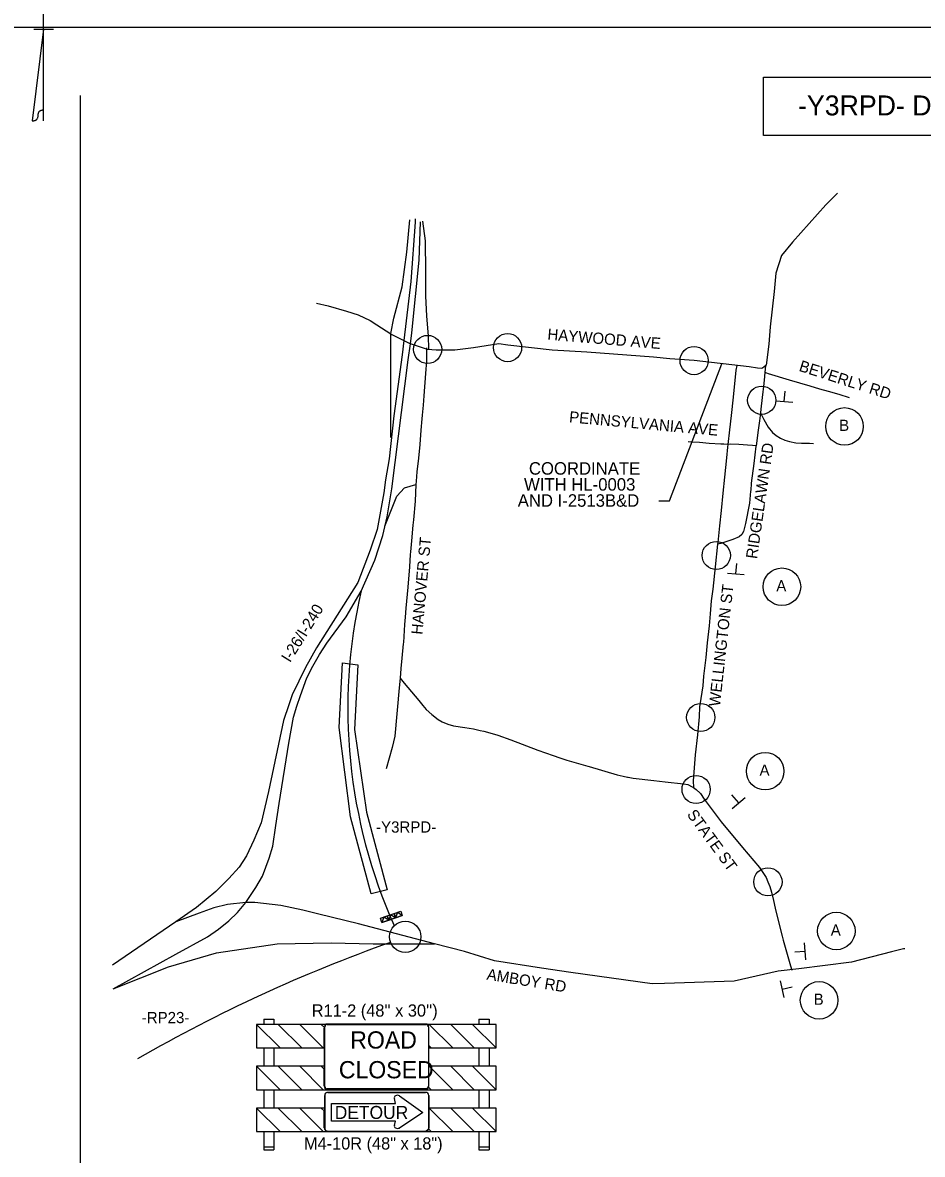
# Model space of a CAD drawing. Extents: x 886234 to 968767, y 455416 to 684046.
# Drawn here: x 922261 to 931269, y 524412 to 535743 of the extents above; entities that cross this region are included whole.
import ezdxf

# ---------------------------------------------------------------- set-up
doc = ezdxf.new("R2010")
doc.units = 0
for name, color, linetype in [('Scratch_Level_3', 7, 'Continuous'), ('TC CONSTRUCTION PROPOSED ROADWAY SHADE', 7, 'Continuous'), ('TC DEV BARRICADE', 7, 'Continuous'), ('TC DEV SIGN', 7, 'Continuous'), ('TC DEV SIGN BLACK 239', 7, 'Continuous'), ('TC DEV SIGN BLACK ZERO', 7, 'Continuous'), ('TC DEV SIGN ORANGE', 7, 'Continuous'), ('TC DEV SIGN WHITE', 7, 'Continuous'), ('TC LABEL TEXT', 7, 'Continuous'), ('TC SHEET LAYOUT SHAPE', 7, 'Continuous')]:
    doc.layers.add(name, color=color, linetype=linetype)

msp = doc.modelspace()

# ---------------------------------------------------------------- linework, layer by layer
at = {"layer": 'Scratch_Level_3'}
msp.add_line((904674, 535699), (939863, 535699), dxfattribs=at)
at = {"layer": 'TC CONSTRUCTION PROPOSED ROADWAY SHADE'}
msp.add_lwpolyline([(925750, 527019), (925544, 527792), (925430, 528686), (925464, 529333), (925617, 529313), (925584, 528666), (925704, 527839), (925910, 527059)], close=True, dxfattribs=at)
at = {"layer": 'TC DEV BARRICADE'}
for p, q in [((925877, 526788), (925911, 526800)), ((925911, 526800), (925945, 526811)), ((925926, 526757), (925911, 526800)), ((925911, 526800), (925926, 526757)), ((925945, 526811), (925926, 526757)), ((925945, 526811), (925980, 526823)), ((925945, 526811), (925945, 526811)), ((925945, 526811), (925945, 526811)), ((925994, 526780), (925945, 526811)), ((925980, 526823), (926013, 526834)), ((925994, 526780), (925980, 526823)), ((925980, 526823), (925994, 526780)), ((926013, 526834), (925994, 526780)), ((926013, 526834), (926048, 526845)), ((926013, 526834), (926013, 526834)), ((926013, 526834), (926013, 526834)), ((926062, 526803), (926013, 526834)), ((926048, 526845), (926062, 526803)), ((925843, 526777), (925877, 526788)), ((925857, 526734), (925843, 526777)), ((925877, 526788), (925857, 526734)), ((925877, 526788), (925877, 526788)), ((925877, 526788), (925877, 526788)), ((925926, 526757), (925877, 526788)), ((924603, 525713), (924603, 525477)), ((924819, 525713), (924603, 525713)), ((924603, 525713), (924839, 525477)), ((927003, 525713), (924603, 525713)), ((924675, 525764), (924777, 525764)), ((924675, 525764), (924675, 525713)), ((924777, 525764), (924777, 525713)), ((925055, 525477), (924819, 525713)), ((925251, 525713), (925035, 525713)), ((925035, 525713), (925271, 525477)), ((925282, 525682), (925251, 525713)), ((925280, 525477), (925280, 525675)), ((926548, 525713), (926332, 525713)), ((926332, 525713), (926567, 525477)), ((926783, 525477), (926548, 525713)), ((927003, 525713), (926764, 525713)), ((926764, 525713), (927003, 525477)), ((926830, 525764), (926932, 525764)), ((926830, 525764), (926830, 525713)), ((926932, 525764), (926932, 525713)), ((927003, 525477), (927003, 525713)), ((927003, 525477), (927003, 525713)), ((924603, 525477), (925280, 525477)), ((924675, 525477), (924675, 525294)), ((924777, 525477), (924777, 525294)), ((924839, 525477), (925055, 525477)), ((925271, 525477), (925280, 525477)), ((926352, 525477), (926327, 525502)), ((926327, 525502), (926327, 525477)), ((926327, 525477), (927003, 525477)), ((926327, 525477), (926352, 525477)), ((926567, 525477), (926783, 525477)), ((926830, 525477), (926830, 525294)), ((926932, 525477), (926932, 525294)), ((924603, 525294), (924603, 525059)), ((924819, 525294), (924603, 525294)), ((924603, 525294), (924839, 525059)), ((925280, 525294), (924603, 525294)), ((925055, 525059), (924819, 525294)), ((925035, 525294), (925271, 525059)), ((925251, 525294), (925035, 525294)), ((925280, 525265), (925251, 525294)), ((925280, 525097), (925280, 525265)), ((927003, 525294), (926327, 525294)), ((926548, 525294), (926332, 525294)), ((926332, 525294), (926567, 525059)), ((926783, 525059), (926548, 525294)), ((927003, 525294), (926764, 525294)), ((926764, 525294), (927003, 525059)), ((927003, 525059), (927003, 525294)), ((927003, 525059), (927003, 525294)), ((924603, 525059), (927003, 525059)), ((924675, 525059), (924675, 524875)), ((924777, 525059), (924777, 524875)), ((924839, 525059), (925055, 525059)), ((925271, 525059), (925341, 525059)), ((926266, 525059), (926352, 525059)), ((926352, 525059), (926324, 525086)), ((926567, 525059), (926783, 525059)), ((926830, 525059), (926830, 524875)), ((926932, 525059), (926932, 524875)), ((924603, 524875), (924603, 524640)), ((924819, 524875), (924603, 524875)), ((924603, 524875), (924839, 524640)), ((925280, 524875), (924603, 524875)), ((925055, 524640), (924819, 524875)), ((925035, 524875), (925271, 524640)), ((925251, 524875), (925035, 524875)), ((925280, 524846), (925251, 524875)), ((927003, 524875), (926327, 524875)), ((926548, 524875), (926332, 524875)), ((926332, 524875), (926567, 524640)), ((926783, 524640), (926548, 524875)), ((927003, 524875), (926764, 524875)), ((926764, 524875), (927003, 524640)), ((927003, 524640), (927003, 524875)), ((927003, 524640), (927003, 524875)), ((925280, 524678), (925280, 524846)), ((926352, 524640), (926324, 524667)), ((924603, 524640), (927003, 524640)), ((924675, 524640), (924675, 524457)), ((924777, 524640), (924777, 524457)), ((924839, 524640), (925055, 524640)), ((925271, 524640), (925341, 524640)), ((926266, 524640), (926352, 524640)), ((926567, 524640), (926783, 524640)), ((926830, 524640), (926830, 524457)), ((926932, 524640), (926932, 524457)), ((924675, 524487), (924777, 524487)), ((924675, 524457), (924777, 524457)), ((926830, 524487), (926932, 524487)), ((926830, 524457), (926932, 524457))]:
    msp.add_line(p, q, dxfattribs=at)
for points in [[(925911, 526800), (925926, 526757), (925857, 526734), (925843, 526777)], [(925980, 526823), (925994, 526780), (925926, 526757), (925911, 526800)], [(925994, 526780), (925945, 526811), (925926, 526757)], [(926048, 526845), (926062, 526803), (925994, 526780), (925980, 526823)], [(926062, 526803), (926013, 526834), (925994, 526780)], [(925926, 526757), (925877, 526788), (925857, 526734)]]:
    msp.add_lwpolyline(points, close=True, dxfattribs=at)
for centre, major_axis, start_param, end_param in [((925341, 525675), (-61, 0), 6.074789, 6.283185), ((925341, 525097), (61, 0), 3.141593, 4.712389), ((926266, 525097), (61, 0), 4.712497, 5.996053), ((925341, 524678), (61, 0), 3.141593, 4.712389), ((926266, 524678), (61, 0), 4.712497, 5.996053)]:
    msp.add_ellipse(centre, major_axis=major_axis, ratio=0.625, start_param=start_param, end_param=end_param, dxfattribs=at)
at = {"layer": 'TC DEV SIGN'}
for p, q in [((929886, 531949), (929895, 532054)), ((929802, 531956), (929971, 531942)), ((929402, 530223), (929411, 530328)), ((929317, 530231), (929486, 530216)), ((929431, 527931), (929363, 528011)), ((929366, 527876), (929496, 527986)), ((930104, 526359), (930089, 526528)), ((930097, 526443), (929992, 526435)), ((929845, 526149), (929883, 525983)), ((929864, 526066), (929967, 526090))]:
    msp.add_line(p, q, dxfattribs=at)
at = {"layer": 'TC DEV SIGN BLACK 239'}
msp.add_line((926300, 525065), (925310, 525065), dxfattribs=at)
for points in [[(925284, 525091), (925284, 525690)], [(925310, 525717), (926300, 525717)], [(926326, 525690), (926326, 525091)]]:
    msp.add_lwpolyline(points, dxfattribs=at)
for centre, start, end in [((925310, 525690), 90, 180), ((926300, 525690), 0, 90), ((925310, 525091), 180, 270.0009), ((926300, 525091), 270.0009, 360)]:
    msp.add_arc(centre, 26.1, start, end, dxfattribs=at)
at = {"layer": 'TC DEV SIGN BLACK ZERO'}
for p, q in [((925286, 525000), (925286, 524674)), ((926295, 525032), (925318, 525032)), ((926033, 524999), (926269, 524831)), ((926328, 524674), (926328, 525000)), ((925352, 524745), (925352, 524920)), ((925352, 524920), (925994, 524920)), ((925994, 524920), (925983, 524972)), ((926269, 524831), (926033, 524675)), ((925993, 524745), (925352, 524745)), ((925983, 524702), (925993, 524745)), ((925318, 524642), (926295, 524642))]:
    msp.add_line(p, q, dxfattribs=at)
for points in [[(925286, 524674), (925286, 525000)], [(925318, 525032), (926295, 525032)], [(926328, 525000), (926328, 524674)], [(926295, 524642), (925318, 524642)]]:
    msp.add_lwpolyline(points, dxfattribs=at)
for centre, start, end in [((925318, 525000), 90, 180), ((925318, 525000), 90, 180), ((926295, 525000), 360, 90), ((926295, 525000), 360, 90), ((925318, 524674), 180, 270), ((925318, 524674), 180, 270), ((926295, 524674), 270, 0), ((926295, 524674), 270, 360)]:
    msp.add_arc(centre, 32.6, start, end, dxfattribs=at)
for centre, start_param, end_param in [((926014, 524979), 0.96961, 3.452569), ((926014, 524695), 2.830617, 5.313577)]:
    msp.add_ellipse(centre, major_axis=(33, 0), ratio=0.720018, start_param=start_param, end_param=end_param, dxfattribs=at)
at = {"layer": 'TC DEV SIGN ORANGE'}
for p, q in [((926033, 524999), (926269, 524831)), ((925352, 524745), (925352, 524920)), ((925352, 524920), (925994, 524920)), ((925994, 524920), (925983, 524972)), ((926269, 524831), (926033, 524675)), ((925993, 524745), (925352, 524745)), ((925983, 524702), (925993, 524745))]:
    msp.add_line(p, q, dxfattribs=at)
for centre, start_param, end_param in [((926014, 524979), 0.96961, 3.452569), ((926014, 524695), 2.830617, 5.313577)]:
    msp.add_ellipse(centre, major_axis=(33, 0), ratio=0.720018, start_param=start_param, end_param=end_param, dxfattribs=at)
at = {"layer": 'TC DEV SIGN WHITE'}
msp.add_line((926300, 525068), (925310, 525068), dxfattribs=at)
for points in [[(925287, 525091), (925287, 525690)], [(925310, 525713), (926300, 525713)], [(926323, 525690), (926323, 525091)]]:
    msp.add_lwpolyline(points, dxfattribs=at)
for centre, start, end in [((925310, 525690), 90, 180), ((926300, 525690), 0, 90), ((925310, 525091), 180, 270.0009), ((926300, 525091), 270.0009, 360)]:
    msp.add_arc(centre, 22.8, start, end, dxfattribs=at)
at = {"layer": 'TC LABEL TEXT'}
for p, q in [((922838, 535015), (922838, 522653)), ((929699, 532308), (929692, 532243))]:
    msp.add_line(p, q, dxfattribs=at)
msp.add_lwpolyline([(929678, 535197), (933060, 535197), (933060, 534613), (929678, 534613)], close=True, dxfattribs=at)
for points in [[(930419, 534036), (930412, 534028), (930304, 533920), (929968, 533545), (929859, 533412), (929802, 533236), (929786, 533052), (929744, 532697), (929732, 532525), (929704, 532314), (929683, 532292), (929661, 532280), (929620, 532282), (929535, 532297), (928984, 532359), (928742, 532378), (928578, 532392), (927910, 532442), (927564, 532462), (927118, 532514), (927028, 532526), (926775, 532488), (926589, 532465), (926403, 532462), (926316, 532471), (926146, 532527)], [(925948, 532631), (925977, 532784), (926060, 533097), (926108, 533444), (926137, 533767)], [(926191, 533779), (926192, 533746), (926148, 533150), (926078, 532560)], [(926146, 532527), (926157, 532637), (926231, 533364), (926246, 533750)], [(926266, 533755), (926290, 533559), (926294, 533249), (926294, 533007), (926303, 532803), (926320, 532608), (926324, 532472)], [(925204, 532934), (925320, 532907), (925505, 532855), (925622, 532817), (925741, 532760), (925806, 532716), (925902, 532658), (925959, 532622), (926078, 532560)], [(925948, 531589), (925948, 532372), (925948, 532484), (925948, 532631)], [(925042, 529007), (925107, 529182), (925166, 529299), (925234, 529417), (925307, 529530), (925500, 529794), (925649, 530052), (925786, 530362), (925868, 530608), (925911, 530796), (925958, 531074), (926121, 532367), (926146, 532527)], [(926078, 532560), (926061, 532417), (925977, 531805), (925930, 531375), (925895, 531164), (925879, 531035), (925809, 530667), (925742, 530461), (925617, 530139)], [(926078, 532560), (926112, 532544), (926146, 532527)], [(926304, 532488), (926304, 532453), (926304, 532356), (926295, 532229), (926277, 532007), (926270, 531914), (926262, 531813), (926259, 531776)], [(928632, 530955), (928736, 530955), (929260, 532328)], [(929413, 532311), (929403, 532263), (929374, 531992), (929356, 531810), (929338, 531666), (929321, 531520)], [(929692, 532243), (929688, 532201), (929681, 532131), (929664, 531991), (929653, 531874), (929649, 531837)], [(929692, 532243), (929725, 532229), (929937, 532167), (930142, 532106), (930238, 532078), (930325, 532054), (930432, 532022), (930536, 531991)], [(929649, 531837), (929640, 531757), (929625, 531661), (929604, 531507)], [(929649, 531837), (929681, 531770), (929726, 531693), (929770, 531639), (929805, 531609), (929848, 531583), (929893, 531564), (929939, 531550), (930002, 531536), (930059, 531534), (930138, 531532), (930179, 531529)], [(926259, 531776), (926249, 531664), (926237, 531518), (926225, 531383), (926209, 531247), (926201, 531152), (926199, 531119)], [(929321, 531520), (929280, 531521), (929252, 531522), (929133, 531528), (929039, 531539), (928965, 531543), (928924, 531546)], [(929321, 531520), (929318, 531493), (929308, 531384), (929289, 531191), (929273, 531032), (929255, 530857), (929238, 530704), (929220, 530537), (929218, 530520)], [(929604, 531507), (929567, 531509), (929518, 531513), (929432, 531520), (929352, 531521), (929321, 531520)], [(929604, 531507), (929603, 531504), (929582, 531329), (929556, 531133), (929551, 531059), (929550, 531051)], [(925889, 530702), (926007, 531001), (926084, 531085), (926199, 531119)], [(926199, 531119), (926191, 530951), (926173, 530766), (926168, 530710), (926153, 530554), (926144, 530445)], [(929550, 531051), (929539, 530933), (929498, 530727), (929480, 530647), (929462, 530617), (929434, 530596), (929370, 530567), (929251, 530528), (929218, 530520)], [(926144, 530445), (926141, 530419), (926133, 530294), (926118, 530090), (926097, 529879), (926090, 529790)], [(929218, 530520), (929194, 530295), (929171, 530071), (929156, 529953), (929143, 529825), (929133, 529704), (929116, 529533), (929100, 529388), (929079, 529199), (929072, 529102), (929052, 528975), (929039, 528893), (929033, 528792), (929018, 528611), (928996, 528412), (928974, 528150), (928977, 528084)], [(925617, 530139), (925204, 529482), (925093, 529285), (924960, 529014), (924925, 528914), (924874, 528757), (924722, 528045), (924648, 527732), (924577, 527556), (924503, 527399), (924429, 527286), (924327, 527172), (924194, 527043), (924002, 526883), (923796, 526740)], [(926090, 529790), (926085, 529716), (926073, 529536)], [(926073, 529536), (926072, 529523), (926059, 529380), (926047, 529276), (926040, 529180)], [(926040, 529180), (926031, 529082), (925987, 528599), (925961, 528484), (925900, 528273)], [(926040, 529180), (926080, 529131), (926228, 528955), (926254, 528922)], [(924495, 526934), (924597, 527082), (924663, 527196), (924730, 527376), (924765, 527497), (924796, 527705), (924831, 527924), (924925, 528530), (924974, 528790), (925008, 528900), (925042, 529007)], [(926254, 528922), (926267, 528906), (926302, 528866), (926357, 528815), (926420, 528767), (926463, 528743), (926517, 528720), (926576, 528703), (926689, 528684), (926774, 528672), (926841, 528657), (926880, 528648), (926916, 528640), (927018, 528609), (927149, 528561), (927419, 528460), (927572, 528404), (927640, 528382), (927710, 528358), (927919, 528297)], [(927919, 528297), (927932, 528294), (928215, 528212), (928274, 528198), (928318, 528188)], [(928318, 528188), (928323, 528187), (928375, 528178), (928582, 528154)], [(928582, 528154), (928694, 528140), (928876, 528121), (928921, 528114), (928965, 528093), (928977, 528084)], [(928977, 528084), (929004, 528065), (929044, 528027), (929047, 528024)], [(929047, 528024), (929086, 527969), (929254, 527742), (929469, 527485), (929637, 527284), (929679, 527225), (929705, 527182), (929723, 527140), (929742, 527094), (929758, 527036), (929778, 526955), (929796, 526878)], [(923169, 526069), (923795, 526417), (924112, 526589), (924221, 526668), (924327, 526750), (924413, 526832), (924495, 526934)], [(924495, 526934), (924311, 526914), (924174, 526879), (924030, 526828), (923796, 526740)], [(926385, 526521), (925623, 526719), (925225, 526816), (925066, 526855), (924847, 526902), (924585, 526934), (924495, 526934)], [(929796, 526878), (929813, 526805), (929866, 526596)], [(923796, 526740), (923162, 526306)], [(929866, 526596), (929876, 526556), (929949, 526299), (929962, 526255)], [(923169, 526069), (923721, 526289), (924202, 526429), (924808, 526519), (925351, 526528), (925771, 526521), (926385, 526521)], [(931093, 526471), (931079, 526468), (930960, 526440), (930561, 526337), (930033, 526270), (929827, 526245), (929385, 526146), (928688, 526122), (928565, 526119), (927750, 526234), (927456, 526277), (926987, 526349), (926686, 526443), (926385, 526521)], [(923169, 526069), (923169, 526069)]]:
    msp.add_lwpolyline(points, dxfattribs=at)
for centre, radius in [((926316, 532471), 141), ((926316, 532471), 141), ((927116, 532489), 141), ((927116, 532489), 141), ((928984, 532359), 141), ((928984, 532359), 141), ((929661, 531962), 141), ((929661, 531962), 141), ((930490, 531700), 188), ((929206, 530408), 141), ((929206, 530408), 141), ((929863, 530095), 188), ((929050, 528786), 141), ((929050, 528786), 141), ((929695, 528248), 188), ((929004, 528065), 141), ((929004, 528065), 141), ((929723, 527140), 141), ((929723, 527140), 141), ((930408, 526648), 188), ((926092, 526590), 157), ((930235, 525954), 188)]:
    msp.add_circle(centre, radius, dxfattribs=at)
for centre, radius, start, end in [((930827, 528874), 5310, 167.1729, 204.1507), ((931077, 512043), 15373, 109.5019, 119.9045)]:
    msp.add_arc(centre, radius, start, end, dxfattribs=at)
at = {"layer": 'TC SHEET LAYOUT SHAPE'}
for p, q in [((922471, 534761), (922471, 536597)), ((922471, 535679), (922358, 534761)), ((922372, 535679), (922569, 535679)), ((922471, 534869), (922471, 535679))]:
    msp.add_line(p, q, dxfattribs=at)
msp.add_open_spline([(922358, 534761), (922415, 534758), (922417, 534870), (922471, 534869)], degree=2, dxfattribs=at)

# ---------------------------------------------------------------- texts
at = {"layer": 'TC DEV BARRICADE'}
for s, p in [("R11-2 (48'' x 30'')", (925156, 525791)), ('M4-10R (48" x 18")', (925078, 524460))]:
    msp.add_text(s, height=122.24, dxfattribs=at).set_placement(p)
at = {"layer": 'TC DEV SIGN BLACK 239'}
for s, p in [('ROAD', (925541, 525471)), ('CLOSED', (925427, 525173))]:
    msp.add_text(s, height=172.6, rotation=360, dxfattribs=at).set_placement(p)
at = {"layer": 'TC DEV SIGN BLACK ZERO'}
msp.add_text('DETOUR', height=130.3, dxfattribs=at).set_placement((925386, 524766))
at = {"layer": 'TC LABEL TEXT'}
for s, height, p in [('-Y3RPD- DETOUR', 200, (930024, 534814)), ('B', 112, (930436, 531655)), ('COORDINATE', 125, (927330, 531217)), ('WITH HL-0003', 125, (927281, 531057)), ('AND I-2513B&D', 125, (927218, 530896)), ('A', 112, (929807, 530049)), ('A', 112, (929639, 528203)), ('-Y3RPD-', 112.5, (925800, 527633)), ('A', 112, (930352, 526602)), ('B', 112, (930181, 525909)), ('-RP23-', 112.5, (923454, 525725))]:
    msp.add_text(s, height=height, dxfattribs=at).set_placement(p)
for s, rotation, p in [('HAYWOOD AVE', 355.2398, (927512, 532569)), ('BEVERLY RD', 342.2909, (930026, 532258)), ('PENNSYLVANIA AVE', 354.8345, (927729, 531741)), ('RIDGELAWN RD', 81.7088, (929613, 530369)), ('HANOVER ST', 84.8458, (926263, 529612)), ('WELLINGTON ST', 83.5989, (929242, 528891)), ('I-26/I-240', 58.0765, (924938, 529329)), ('STATE ST', 306.1918, (928907, 527814)), ('AMBOY RD', 350.7417, (926902, 526162))]:
    msp.add_text(s, height=112.5, rotation=rotation, dxfattribs=at).set_placement(p)

doc.saveas('drawing.dxf')
